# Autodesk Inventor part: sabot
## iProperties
Created: 2011-09
Part Number: sabot
Document SubType Name: Modeling
Designer: Dominique
Author: Dominique
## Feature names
1. Extrusion1
2. Chanfrein1 [Chamfer]
3. Extrusion2
4. Extrusion3
5. Extrusion4
6. Extrusion5
7. Perçage1 [Hole]
